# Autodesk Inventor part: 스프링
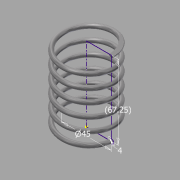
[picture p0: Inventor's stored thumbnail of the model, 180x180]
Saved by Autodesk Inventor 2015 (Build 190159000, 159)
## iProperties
Created: 2016-02
Part Number: 스프링
Material: 스테인레스 스틸
Document SubType Name: Modeling
Designer: Administrator
Mass: 84.1975 g
Surface Area: 106.451 cm^2
Volume: 10.5247 cm^3
Density: 8 g/cm^3
Appearance: 반연마
Author: Administrator
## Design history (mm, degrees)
sketch "스케치1"
  geometry: L1 (0, 67.25)-(-22.5, 67.25); L2 (-22.5, 67.25)-(-22.5, 0); L3 (-22.5, 0)-(0, 0); L4 (0, 0)-(0, 67.25); C1 r 2 at (-22.5, 0); 1 further point
  constraints: 8 end point, 2 coincident, 2 parallel, 1 centre point, 1 horizontal, 1 perpendicular
  dimensions: "d0" = 45 diameter of L2 L4; "d1" = 67.25 distance of L1.end L2.end (derived); "d2" = 4 diameter of C1
feature "코일1" sketch "스케치1" pitch "d3" = 10; turns "d5" = 6; dims "d4" = 67.25 (= d1), "d6" = 0, angle "d7" = 90 deg, angle "d8" = 90 deg, "d9" = 0, "d10" = 0
sketch "스케치2"
  geometry: L1 (20.5, 0)-(24.5, 0) reference; 1 further point
  constraints: 1 horizontal alignment
extrude "돌출1" cut sketch "스케치2" stored distance "d11" = 10; taper "d12" = 0 deg
node "작업 평면1"
sketch "스케치3"
  geometry: L1 (2, 0)-(-2, 0) reference; 1 further point
  constraints: 1 horizontal alignment
extrude "돌출2" cut sketch "스케치3" stored distance "d13" = 10; taper "d14" = 0 deg
node "솔리드1"
node "절단 모서리 투영1"
node "절단 모서리 투영2"
